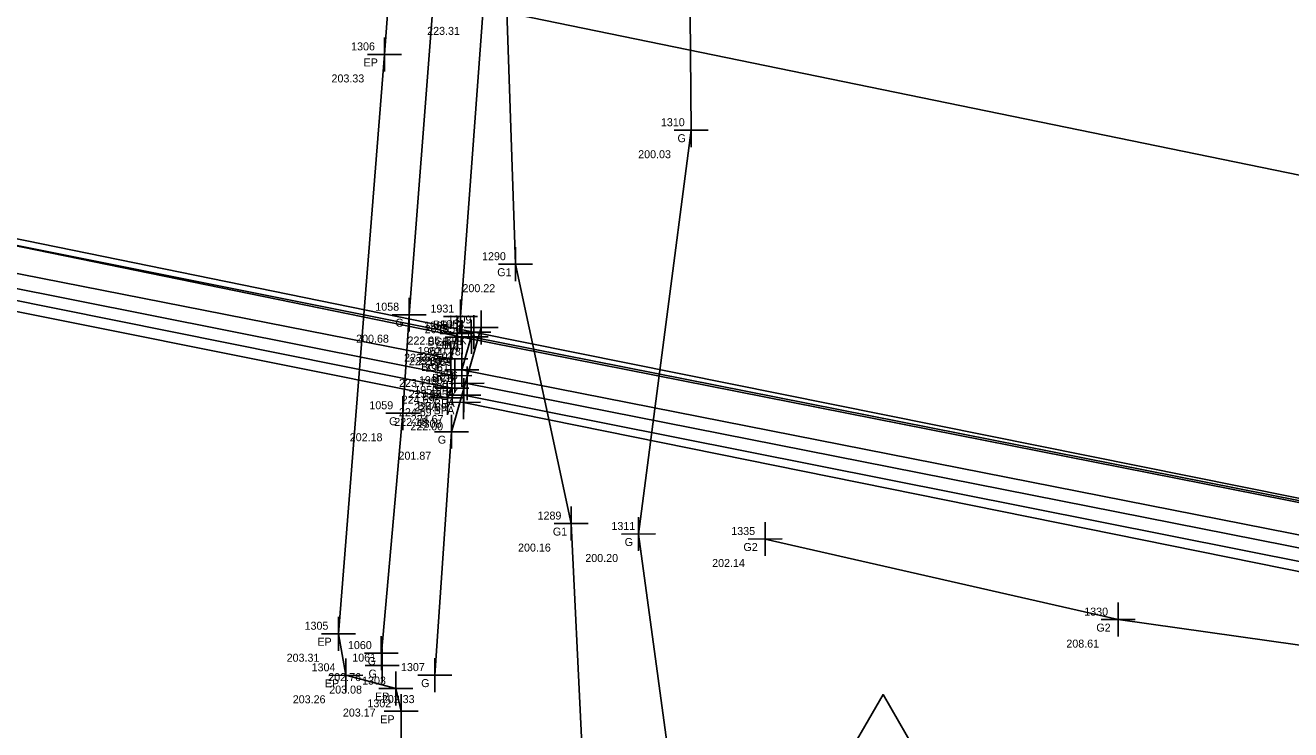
# Model space of a CAD drawing. Extents: x 1158983 to 1160032, y 610902 to 611573.
# Drawn here: x 1159613.25 to 1159660.69, y 611189.89 to 611216.31 of the extents above; entities that cross this region are included whole.
import ezdxf

# ---------------------------------------------------------------- set-up
doc = ezdxf.new("R2010")
doc.units = 0
for name, color, linetype in [('S_Bridge_Centerline', 7, 'Continuous'), ('S_Bridge_Curb', 7, 'Continuous'), ('S_Bridge_Deck', 7, 'Continuous'), ('S_Bridge_ExpansionJoint', 7, 'Continuous'), ('S_Bridge_Fascia', 7, 'Continuous'), ('S_Control_Temp_Traverse', 7, 'Continuous'), ('S_Field_Code', 7, 'Continuous'), ('S_Ground_Elevation', 7, 'Continuous'), ('S_Guardrail_Beam', 7, 'Continuous'), ('S_Misc_MiscFeature', 7, 'Continuous'), ('S_Point_Elevation', 7, 'Continuous'), ('S_Point_Name', 7, 'Continuous'), ('S_Roadway_Edge_Pavement', 7, 'Continuous'), ('S_Survey_Shot', 7, 'Continuous')]:
    doc.layers.add(name, color=color, linetype=linetype)

msp = doc.modelspace()

# ---------------------------------------------------------------- linework, layer by layer
at = {"layer": 'S_Bridge_Centerline'}
msp.add_lwpolyline([(1159333.27, 611277.49), (1159375.085, 611269.079), (1159432.648, 611257.515), (1159502.769, 611243.159), (1159572.889, 611228.86), (1159630.259, 611216.999), (1159672.294, 611208.379)], dxfattribs=at)
at = {"layer": 'S_Bridge_Curb'}
for points in [[(1159629.205, 611203.795), (1159629.444, 611204.744), (1159572.582, 611216.126), (1159572.35, 611214.988)], [(1159672.265, 611194.975), (1159672.481, 611196.211), (1159629.974, 611204.626), (1159629.621, 611203.384)]]:
    msp.add_lwpolyline(points, close=True, dxfattribs=at)
at = {"layer": 'S_Bridge_Deck'}
msp.add_lwpolyline([(1159333.801, 611289.348), (1159375.965, 611280.699), (1159433.546, 611269.247), (1159503.551, 611254.972), (1159573.652, 611240.691), (1159630.945, 611229.008), (1159674.004, 611220.503), (1159672.341, 611196.28), (1159630.068, 611204.797), (1159572.75, 611216.514), (1159502.493, 611230.859), (1159432.439, 611245.062), (1159375.072, 611256.503), (1159331.888, 611265.329)], close=True, dxfattribs=at)
at = {"layer": 'S_Bridge_ExpansionJoint'}
msp.add_lwpolyline([(1159631.293, 611228.785), (1159629.57, 611205.385)], dxfattribs=at)
at = {"layer": 'S_Bridge_Fascia'}
for points in [[(1159629.075, 611202.332), (1159629.25, 611202.698), (1159572.412, 611214.138), (1159572.253, 611213.727)], [(1159672.101, 611193.576), (1159672.004, 611194.007), (1159629.69, 611202.438), (1159629.678, 611202.167)]]:
    msp.add_lwpolyline(points, close=True, dxfattribs=at)
at = {"layer": 'S_Control_Temp_Traverse'}
msp.add_lwpolyline([(1159643.679, 611188.213), (1159647.136, 611188.213), (1159645.407, 611191.207)], close=True, dxfattribs=at)
at = {"layer": 'S_Ground_Elevation'}
for points in [[(1159630.127, 611238.015), (1159629.448, 611228.837), (1159627.645, 611205.454), (1159627.406, 611201.758), (1159626.601, 611192.763), (1159626.636, 611192.293)], [(1159631.631, 611207.348), (1159630.736, 611233.672)], [(1159638.219, 611212.373), (1159638.083, 611228.261)], [(1159638.219, 611212.373), (1159636.237, 611197.229), (1159638.417, 611181.257), (1159645.223, 611166.982), (1159655.488, 611154.766), (1159667.117, 611150.624)], [(1159639.791, 610965.535), (1159645.775, 610991.151), (1159650.157, 611007.062), (1159651.628, 611033.422), (1159658.582, 611070.749), (1159658.53, 611093.77), (1159652.818, 611125.693), (1159649.858, 611152.31), (1159637.568, 611166.545), (1159634.492, 611181.577), (1159633.715, 611197.62), (1159631.631, 611207.348)], [(1159628.609, 611191.937), (1159629.233, 611201.066), (1159630.339, 611204.975)], [(1159671.448, 611191.835), (1159665.451, 611192.436), (1159654.219, 611194.018), (1159640.99, 611197.041)]]:
    msp.add_lwpolyline(points, dxfattribs=at)
at = {"layer": 'S_Guardrail_Beam'}
msp.add_lwpolyline([(1159962.355, 611128.723), (1159954.927, 611131.331), (1159940.804, 611136.335), (1159922.846, 611140.981), (1159878.137, 611150.269), (1159824.181, 611161.329), (1159771.192, 611171.967), (1159724.558, 611182.82), (1159696.585, 611190.71), (1159683.564, 611193.82), (1159671.877, 611196.264), (1159629.625, 611204.61), (1159571.633, 611216.492), (1159501.577, 611230.682), (1159431.638, 611244.705), (1159374.182, 611256.374), (1159332.105, 611265.121)], dxfattribs=at)
at = {"layer": 'S_Misc_MiscFeature'}
for points in [[(1159629.354, 611203.167), (1159572.432, 611214.501)], [(1159672.181, 611194.494), (1159629.815, 611202.879)]]:
    msp.add_lwpolyline(points, dxfattribs=at)
at = {"layer": 'S_Roadway_Edge_Pavement'}
for points in [[(1159628.504, 611239.183), (1159626.722, 611215.216)], [(1159649.054, 610914.248), (1159642.457, 610938.482), (1159637.798, 610964.216), (1159632.683, 610994.591), (1159630.828, 611030.062), (1159633.705, 611071.605), (1159635.455, 611089.542), (1159635.84, 611098.138), (1159632.325, 611112.966), (1159628.263, 611134.867), (1159627.396, 611158.056), (1159627.348, 611190.58), (1159627.149, 611191.432), (1159625.27, 611191.93), (1159624.992, 611193.489), (1159626.722, 611215.216)]]:
    msp.add_lwpolyline(points, dxfattribs=at)
at = {"layer": 'S_Survey_Shot'}
for p, q in [((1159626.723, 611214.58), (1159626.721, 611215.853)), ((1159626.086, 611215.215), (1159627.358, 611215.218)), ((1159626.722, 611215.216), (1159626.722, 611215.216)), ((1159638.221, 611211.737), (1159638.218, 611213.01)), ((1159637.583, 611212.372), (1159638.855, 611212.375)), ((1159638.219, 611212.373), (1159638.219, 611212.373)), ((1159631.633, 611206.712), (1159631.63, 611207.985)), ((1159630.995, 611207.347), (1159632.267, 611207.35)), ((1159631.631, 611207.348), (1159631.631, 611207.348)), ((1159627.646, 611204.818), (1159627.643, 611206.09)), ((1159629.571, 611204.749), (1159629.568, 611206.022)), ((1159627.009, 611205.453), (1159628.281, 611205.455)), ((1159627.645, 611205.454), (1159627.645, 611205.454)), ((1159630.07, 611204.161), (1159630.067, 611205.433)), ((1159630.34, 611204.339), (1159630.337, 611205.611)), ((1159628.934, 611205.384), (1159630.206, 611205.387)), ((1159629.446, 611204.108), (1159629.443, 611205.38)), ((1159629.57, 611205.385), (1159629.57, 611205.385)), ((1159629.626, 611203.974), (1159629.624, 611205.246)), ((1159629.703, 611204.974), (1159630.975, 611204.976)), ((1159629.976, 611203.99), (1159629.973, 611205.262)), ((1159630.339, 611204.975), (1159630.339, 611204.975)), ((1159628.808, 611204.743), (1159630.081, 611204.745)), ((1159628.989, 611204.608), (1159630.261, 611204.611)), ((1159629.338, 611204.625), (1159630.61, 611204.627)), ((1159629.432, 611204.796), (1159630.704, 611204.798)), ((1159629.444, 611204.744), (1159629.444, 611204.744)), ((1159629.625, 611204.61), (1159629.625, 611204.61)), ((1159629.974, 611204.626), (1159629.974, 611204.626)), ((1159630.068, 611204.797), (1159630.068, 611204.797)), ((1159629.207, 611203.159), (1159629.204, 611204.431)), ((1159629.623, 611202.748), (1159629.62, 611204.02)), ((1159628.569, 611203.794), (1159629.841, 611203.797)), ((1159629.205, 611203.795), (1159629.205, 611203.795)), ((1159629.355, 611202.531), (1159629.353, 611203.803)), ((1159628.718, 611203.166), (1159629.99, 611203.169)), ((1159628.985, 611203.383), (1159630.257, 611203.385)), ((1159629.251, 611202.062), (1159629.249, 611203.335)), ((1159629.354, 611203.167), (1159629.354, 611203.167)), ((1159629.621, 611203.384), (1159629.621, 611203.384)), ((1159629.692, 611201.802), (1159629.689, 611203.074)), ((1159629.817, 611202.243), (1159629.814, 611203.515)), ((1159628.614, 611202.697), (1159629.886, 611202.7)), ((1159629.077, 611201.696), (1159629.074, 611202.968)), ((1159629.179, 611202.878), (1159630.452, 611202.881)), ((1159629.25, 611202.698), (1159629.25, 611202.698)), ((1159629.679, 611201.531), (1159629.677, 611202.804)), ((1159629.815, 611202.879), (1159629.815, 611202.879)), ((1159627.407, 611201.121), (1159627.405, 611202.394)), ((1159628.439, 611202.331), (1159629.712, 611202.333)), ((1159629.042, 611202.166), (1159630.314, 611202.169)), ((1159629.054, 611202.437), (1159630.327, 611202.44)), ((1159629.075, 611202.332), (1159629.075, 611202.332)), ((1159629.678, 611202.167), (1159629.678, 611202.167)), ((1159629.69, 611202.438), (1159629.69, 611202.438)), ((1159626.77, 611201.756), (1159628.042, 611201.759)), ((1159627.406, 611201.758), (1159627.406, 611201.758)), ((1159629.234, 611200.43), (1159629.232, 611201.702)), ((1159628.597, 611201.065), (1159629.869, 611201.067)), ((1159629.233, 611201.066), (1159629.233, 611201.066)), ((1159633.716, 611196.984), (1159633.713, 611198.257)), ((1159636.239, 611196.593), (1159636.236, 611197.866)), ((1159633.078, 611197.619), (1159634.351, 611197.622)), ((1159633.715, 611197.62), (1159633.715, 611197.62)), ((1159640.991, 611196.405), (1159640.988, 611197.677)), ((1159635.601, 611197.228), (1159636.874, 611197.231)), ((1159636.237, 611197.229), (1159636.237, 611197.229)), ((1159640.353, 611197.039), (1159641.626, 611197.042)), ((1159640.99, 611197.041), (1159640.99, 611197.041)), ((1159654.221, 611193.382), (1159654.218, 611194.655)), ((1159624.993, 611192.853), (1159624.99, 611194.126)), ((1159653.583, 611194.017), (1159654.855, 611194.02)), ((1159654.219, 611194.018), (1159654.219, 611194.018)), ((1159624.356, 611193.488), (1159625.628, 611193.491)), ((1159624.992, 611193.489), (1159624.992, 611193.489)), ((1159626.602, 611192.127), (1159626.599, 611193.4)), ((1159625.964, 611192.762), (1159627.237, 611192.765)), ((1159626.601, 611192.763), (1159626.601, 611192.763)), ((1159626.638, 611191.657), (1159626.635, 611192.93)), ((1159625.272, 611191.293), (1159625.269, 611192.566)), ((1159626, 611192.292), (1159627.273, 611192.295)), ((1159626.636, 611192.293), (1159626.636, 611192.293)), ((1159628.61, 611191.301), (1159628.607, 611192.573)), ((1159624.634, 611191.928), (1159625.907, 611191.931)), ((1159625.27, 611191.93), (1159625.27, 611191.93)), ((1159627.15, 611190.796), (1159627.147, 611192.068)), ((1159627.973, 611191.936), (1159629.245, 611191.938)), ((1159628.609, 611191.937), (1159628.609, 611191.937)), ((1159626.512, 611191.43), (1159627.785, 611191.433)), ((1159627.149, 611191.432), (1159627.149, 611191.432)), ((1159627.349, 611189.944), (1159627.347, 611191.216)), ((1159626.712, 611190.579), (1159627.984, 611190.582)), ((1159627.348, 611190.58), (1159627.348, 611190.58))]:
    msp.add_line(p, q, dxfattribs=at)

# ---------------------------------------------------------------- texts
at = {"layer": 'S_Field_Code'}
for s, p in [('EP', (1159625.936, 611214.766)), ('G', (1159637.704, 611211.923)), ('G1', (1159630.946, 611206.898)), ('G', (1159627.13, 611205.004)), ('BEJ', (1159628.54, 611204.935)), ('BCB', (1159628.329, 611204.294)), ('BDK', (1159628.967, 611204.347)), ('G', (1159629.824, 611204.525)), ('GB1', (1159628.64, 611204.16)), ('BCB', (1159628.859, 611204.176)), ('BCB', (1159628.09, 611203.345)), ('BCB', (1159628.506, 611202.934)), ('ZZ', (1159628.553, 611202.717)), ('ZZ', (1159629.015, 611202.429)), ('BFA', (1159627.958, 611201.882)), ('BFA', (1159628.133, 611202.248)), ('BFA', (1159628.573, 611201.988)), ('BFA', (1159628.561, 611201.717)), ('G', (1159626.891, 611201.308)), ('G', (1159628.718, 611200.616)), ('G1', (1159633.03, 611197.17)), ('G', (1159635.722, 611196.779)), ('G2', (1159640.175, 611196.591)), ('G2', (1159653.404, 611193.568)), ('EP', (1159624.205, 611193.039)), ('G', (1159626.086, 611192.313)), ('EP', (1159624.484, 611191.48)), ('G', (1159626.122, 611191.843)), ('G', (1159628.094, 611191.487)), ('EP', (1159626.362, 611190.982)), ('EP', (1159626.561, 611190.13))]:
    msp.add_text(s, height=0.3, dxfattribs=at).set_placement(p)
at = {"layer": 'S_Point_Elevation'}
for s, p in [('223.31', (1159628.32, 611215.949)), ('203.33', (1159624.733, 611214.166)), ('200.03', (1159636.23, 611211.323)), ('200.22', (1159629.642, 611206.298)), ('200.68', (1159625.656, 611204.404)), ('222.95', (1159627.581, 611204.335)), ('223.03', (1159628.079, 611203.747)), ('200.48', (1159628.35, 611203.925)), ('223.67', (1159627.455, 611203.694)), ('223.66', (1159627.636, 611203.56)), ('223.64', (1159627.985, 611203.576)), ('223.71', (1159627.266, 611202.745)), ('223.68', (1159627.632, 611202.334)), ('224.69', (1159627.365, 611202.117)), ('224.69', (1159627.827, 611201.829)), ('224.69', (1159627.261, 611201.648)), ('224.67', (1159627.702, 611201.388)), ('222.18', (1159627.086, 611201.282)), ('222.00', (1159627.689, 611201.117)), ('202.18', (1159625.417, 611200.708)), ('201.87', (1159627.244, 611200.016)), ('200.16', (1159631.726, 611196.57)), ('200.20', (1159634.248, 611196.179)), ('202.14', (1159639.001, 611195.991)), ('208.61', (1159652.28, 611192.968)), ('203.31', (1159623.052, 611192.439)), ('202.76', (1159624.612, 611191.713)), ('203.08', (1159624.648, 611191.243)), ('203.26', (1159623.281, 611190.88)), ('202.33', (1159626.62, 611190.887)), ('203.17', (1159625.16, 611190.382))]:
    msp.add_text(s, height=0.3, dxfattribs=at).set_placement(p)
at = {"layer": 'S_Point_Name'}
for s, p in [('1306', (1159625.468, 611215.367)), ('1310', (1159637.081, 611212.523)), ('1290', (1159630.377, 611207.498)), ('1058', (1159626.376, 611205.604)), ('1931', (1159628.443, 611205.535)), ('1963', (1159628.202, 611204.894)), ('2035', (1159628.227, 611204.76)), ('1954', (1159628.703, 611204.776)), ('1953', (1159628.812, 611204.947)), ('1309', (1159629.085, 611205.125)), ('1962', (1159627.963, 611203.945)), ('1961', (1159628.242, 611203.317)), ('1955', (1159628.365, 611203.534)), ('1960', (1159628.01, 611202.848)), ('1956', (1159628.573, 611203.029)), ('1959', (1159627.833, 611202.482)), ('1958', (1159628.421, 611202.317)), ('1957', (1159628.432, 611202.588)), ('1059', (1159626.152, 611201.908)), ('1308', (1159627.964, 611201.216)), ('1289', (1159632.458, 611197.77)), ('1311', (1159635.226, 611197.379)), ('1335', (1159639.719, 611197.191)), ('1330', (1159652.951, 611194.168)), ('1305', (1159623.723, 611193.639)), ('1060', (1159625.349, 611192.913)), ('1061', (1159625.512, 611192.443)), ('1304', (1159623.988, 611192.08)), ('1307', (1159627.338, 611192.087)), ('1303', (1159625.88, 611191.582)), ('1302', (1159626.08, 611190.73))]:
    msp.add_text(s, height=0.3, dxfattribs=at).set_placement(p)

doc.saveas('drawing.dxf')
